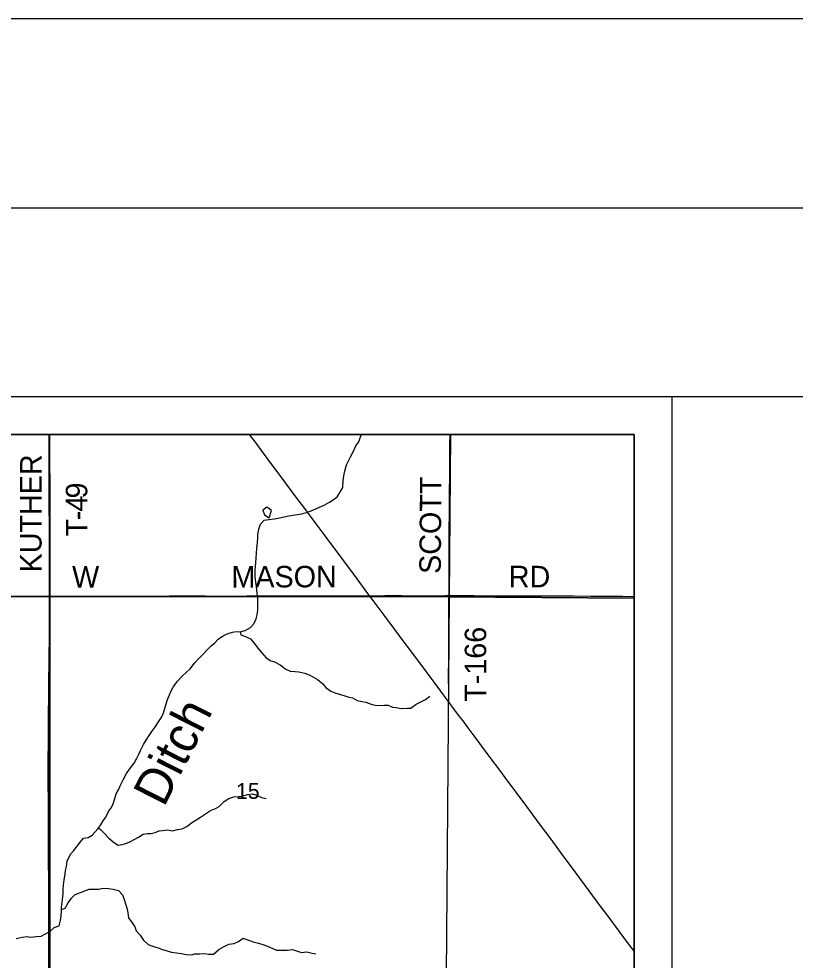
# Model space of a CAD drawing. Extents: x 0 to 1391, y -24 to 440.
# Drawn here: x 445.46 to 486.52, y 390.17 to 440 of the extents above; entities that cross this region are included whole.
import ezdxf

# ---------------------------------------------------------------- set-up
doc = ezdxf.new("R2010")
doc.units = 0
for name, color, linetype in [('Default', 7, 'Continuous'), ('GM_X_County_Road', 7, 'Continuous'), ('GM_X_County_Road_Text', 7, 'Continuous'), ('GM_X_Minor_Lake', 7, 'Continuous'), ('GM_X_Minor_River', 7, 'Continuous'), ('GM_X_Minor_River_Text', 7, 'Continuous'), ('GM_X_Section', 7, 'Continuous'), ('GM_X_Section_Text', 7, 'Continuous'), ('GM_X_State_Route', 7, 'Continuous'), ('GM_X_Township', 7, 'Continuous'), ('GM_X_Township_Road', 7, 'Continuous'), ('GM_X_Township_Road_Text', 7, 'Continuous'), ('SH_Border', 7, 'Continuous'), ('SH_Cut_Line', 7, 'Continuous'), ('SH_Data', 7, 'Continuous')]:
    doc.layers.add(name, color=color, linetype=linetype)

msp = doc.modelspace()

# ---------------------------------------------------------------- linework, layer by layer
at = {"layer": 'Default'}
msp.add_line((480, 420), (490, 420), dxfattribs=at)
at = {"layer": 'GM_X_County_Road'}
for points in [[(444.5, 409.44), (445.793, 409.438), (446.526, 409.432), (447.1, 409.437)], [(447.1, 409.437), (447.737, 409.441), (449.228, 409.441), (450.024, 409.439), (450.471, 409.445), (451.676, 409.442), (453.404, 409.448), (455.305, 409.45), (456.373, 409.446), (457.492, 409.453), (457.889, 409.452), (458.61, 409.453), (459.828, 409.457), (460.785, 409.457), (461.941, 409.458), (462.649, 409.459), (463.519, 409.456), (463.929, 409.458), (463.994, 409.459)], [(463.994, 409.459), (464.153, 409.461), (464.811, 409.468), (465.718, 409.467), (466.961, 409.464), (468.017, 409.467), (468.214, 409.466)], [(468.214, 409.466), (468.9, 409.465), (469.546, 409.465), (470.391, 409.462), (472.23, 409.462), (473.013, 409.458), (473.933, 409.457), (474.79, 409.452), (475.697, 409.444), (476.542, 409.439), (477.399, 409.433), (478, 409.426)]]:
    msp.add_lwpolyline(points, dxfattribs=at)
at = {"layer": 'GM_X_Minor_Lake'}
for points in [[(458.821, 413.968), (458.574, 414.149), (458.356, 413.993)], [(458.356, 413.993), (458.453, 413.735), (458.701, 413.586), (458.821, 413.968)]]:
    msp.add_lwpolyline(points, dxfattribs=at)
at = {"layer": 'GM_X_Minor_River'}
for points in [[(455.211, 406.369), (455.426, 406.594), (455.626, 406.812), (455.818, 406.969), (456.002, 407.164), (456.232, 407.328), (456.469, 407.446), (456.759, 407.534), (456.958, 407.562), (457.171, 407.559), (457.43, 407.617), (457.706, 407.773), (457.883, 407.976), (458.015, 408.247), (458.062, 408.451), (458.095, 408.693), (458.105, 409.027), (458.101, 409.36), (458.057, 409.588), (458.03, 409.952), (457.986, 410.173), (457.951, 410.484), (457.954, 410.832), (457.996, 411.211), (458.006, 411.476), (458.023, 411.711), (458.048, 411.968), (458.074, 412.286), (458.091, 412.513), (458.108, 412.71), (458.156, 412.983), (458.242, 413.247), (458.442, 413.457), (458.686, 413.499), (458.984, 413.534), (459.243, 413.584), (459.495, 413.642), (459.731, 413.692), (460.067, 413.741), (460.418, 413.805), (460.677, 413.871), (460.922, 413.959), (461.166, 414.07), (461.357, 414.158), (461.602, 414.254), (461.885, 414.41), (462.077, 414.544), (462.299, 414.693), (462.469, 414.972), (462.593, 415.19), (462.619, 415.569), (462.652, 415.803), (462.707, 416.053), (462.786, 416.385), (462.903, 416.611), (463.003, 416.815), (463.151, 417.109), (463.291, 417.395), (463.437, 417.613), (463.531, 417.87), (463.585, 418)], [(457.171, 407.559), (457.208, 407.391), (457.443, 407.312), (457.708, 407.171), (457.91, 406.955), (458.105, 406.679), (458.3, 406.449), (458.547, 406.18), (458.788, 406.009), (458.986, 405.96), (459.28, 405.804), (459.582, 405.572), (459.801, 405.47), (460.067, 405.443), (460.272, 405.439), (460.583, 405.366), (460.818, 405.271), (461.014, 405.17), (461.248, 405.022), (461.512, 404.813), (461.692, 404.606), (461.963, 404.412), (462.228, 404.309), (462.418, 404.253), (462.706, 404.165), (462.91, 404.086), (463.1, 404.06), (463.357, 403.919), (463.622, 403.87), (463.82, 403.821), (464.092, 403.726), (464.305, 403.677), (464.533, 403.651), (464.776, 403.677), (464.997, 403.673), (465.224, 403.556), (465.421, 403.538), (465.679, 403.496), (466.006, 403.513), (466.197, 403.518), (466.466, 403.726), (466.718, 403.836), (466.963, 403.976), (467.201, 404.146)], [(445.318, 391.311), (445.654, 391.391), (445.882, 391.418), (446.095, 391.386), (446.37, 391.42), (446.636, 391.44), (446.828, 391.544), (447.095, 391.693), (447.333, 391.895), (447.593, 391.983), (447.664, 392.27), (447.696, 392.52), (447.714, 392.785), (447.715, 392.982), (447.748, 393.248), (447.781, 393.52), (447.798, 393.717), (447.807, 393.93), (447.824, 394.142), (447.857, 394.414), (447.905, 394.717), (447.93, 394.914), (447.977, 395.133), (448.01, 395.414), (448.181, 395.776), (448.365, 395.978), (448.542, 396.196), (448.72, 396.429), (448.874, 396.625), (449.125, 396.66), (449.34, 396.794), (449.639, 397.116), (449.786, 397.334), (449.925, 397.538), (450.056, 397.741), (450.196, 398.042), (450.357, 398.245), (450.45, 398.441), (450.529, 398.721), (450.607, 398.97), (450.723, 399.189), (450.824, 399.4), (450.972, 399.709), (451.157, 400.056), (451.304, 400.282), (451.55, 400.59), (451.698, 400.868), (451.813, 401.072), (451.899, 401.268), (452.046, 401.585), (452.201, 401.81), (452.355, 402.066), (452.487, 402.277), (452.648, 402.487), (452.88, 402.841), (453.019, 403.059), (453.105, 403.271), (453.183, 403.497), (453.246, 403.731), (453.316, 403.966), (453.418, 404.222), (453.518, 404.426), (453.627, 404.629), (453.858, 404.945), (454.104, 405.207), (454.334, 405.409), (454.526, 405.589), (454.742, 405.89), (454.98, 406.137), (455.211, 406.369)], [(449.673, 397.167), (449.801, 397.07), (449.981, 396.87), (450.206, 396.654), (450.462, 396.415), (450.719, 396.251), (450.917, 396.294), (451.169, 396.365), (451.36, 396.446), (451.552, 396.564), (451.781, 396.674), (452.042, 396.837), (452.263, 396.871), (452.453, 396.868), (452.667, 396.933), (452.881, 397.013), (453.071, 397.04), (453.315, 397.074), (453.588, 397.017), (453.848, 397.088), (454.099, 397.13), (454.344, 397.247), (454.59, 397.433), (454.782, 397.559), (455.073, 397.743), (455.334, 397.914), (455.587, 398.084), (455.854, 398.201), (456.054, 398.312), (456.323, 398.573), (456.561, 398.721), (456.828, 398.815), (457.087, 398.826), (457.323, 398.875), (457.56, 398.947), (457.811, 398.966), (458.001, 398.917), (458.288, 398.784), (458.546, 398.734)], [(447.714, 392.848), (447.902, 392.929), (448.065, 393.2), (448.235, 393.447), (448.443, 393.641), (448.711, 393.743), (448.948, 393.838), (449.169, 393.933), (449.451, 393.928), (449.687, 393.932), (449.893, 393.982), (450.197, 393.962), (450.455, 393.927), (450.735, 393.862), (450.946, 393.623), (451.034, 393.379), (451.195, 392.861), (451.215, 392.671), (451.258, 392.405), (451.46, 392.151), (451.587, 391.937), (451.668, 391.723), (451.878, 391.5), (452.057, 391.224), (452.306, 391.007), (452.639, 390.873), (452.828, 390.825), (453.048, 390.73), (453.351, 390.642), (453.541, 390.601), (453.799, 390.566), (454.057, 390.524), (454.307, 390.467), (454.573, 390.448), (454.764, 390.505), (455.031, 390.509), (455.297, 390.519), (455.487, 390.486), (455.753, 390.482), (456.03, 390.728), (456.275, 390.883), (456.558, 391.015), (456.84, 391.056), (457.069, 391.151), (457.33, 391.337), (457.656, 391.217), (457.853, 391.146), (458.141, 391.073), (458.368, 390.994), (458.61, 390.906), (458.89, 390.781), (459.087, 390.702), (459.361, 390.697), (459.65, 390.7), (459.939, 390.726), (460.197, 390.638), (460.417, 390.567), (460.691, 390.608), (460.979, 390.535), (461.169, 390.501)]]:
    msp.add_lwpolyline(points, dxfattribs=at)
at = {"layer": 'GM_X_Section'}
for p, q in [((447.083, 418), (426.829, 418)), ((468.284, 418), (447.083, 418)), ((478, 389.026), (478, 409.34))]:
    msp.add_line(p, q, dxfattribs=at)
for points in [[(426.829, 418), (426.856, 409.369), (447.091, 409.422), (447.083, 418)], [(447.083, 418), (447.091, 409.422), (468.226, 409.405), (468.284, 418)], [(468.284, 418), (468.226, 409.405), (478, 409.34)], [(478, 409.34), (478, 418), (468.284, 418)], [(478, 409.34), (468.226, 409.405), (468.063, 389.349), (478, 389.026)]]:
    msp.add_lwpolyline(points, dxfattribs=at)
for points in [[(447.091, 409.422), (447.091, 389.196), (426.804, 389.204), (426.856, 409.369)], [(468.226, 409.405), (468.063, 389.349), (447.091, 389.196), (447.091, 409.422)]]:
    msp.add_lwpolyline(points, close=True, dxfattribs=at)
at = {"layer": 'GM_X_State_Route'}
msp.add_lwpolyline([(457.64, 418), (457.95, 417.584), (458.375, 417.002), (458.826, 416.408), (459.314, 415.749), (459.594, 415.369), (460.096, 414.705), (460.568, 414.079), (461.116, 413.341), (461.641, 412.632), (462.523, 411.445), (463.135, 410.615), (463.671, 409.898), (463.994, 409.459), (464.127, 409.277), (464.812, 408.362), (465.327, 407.676), (465.831, 406.998), (466.124, 406.612), (466.995, 405.432), (467.76, 404.406), (468.093, 403.956), (468.196, 403.817), (468.381, 403.567), (468.775, 403.054), (468.941, 402.837), (469.154, 402.546), (469.52, 402.044), (470.427, 400.829), (470.829, 400.292), (471.354, 399.583), (472.109, 398.564), (473.035, 397.317), (473.59, 396.568), (474.148, 395.821), (474.865, 394.853), (475.61, 393.843), (476.244, 392.983), (476.56, 392.567), (476.815, 392.23), (477.642, 391.111), (478, 390.634)], dxfattribs=at)
at = {"layer": 'GM_X_Township'}
for points in [[(447.02, 384.234), (447.036, 389.216), (447.076, 409.404), (447.056, 418), (367.289, 418), (367.16, 409.322), (367.112, 389.089), (367.052, 379.006), (366.961, 368.979), (366.895, 354.384)], [(447.056, 418), (447.076, 409.404), (447.036, 389.216), (451.2, 389.137), (459.724, 389.173), (463.069, 389.137), (465.594, 389.22), (467.732, 389.301), (470.436, 389.153), (473.97, 389.031), (478, 388.948)], [(478, 388.948), (478, 418), (447.056, 418)]]:
    msp.add_lwpolyline(points, dxfattribs=at)
at = {"layer": 'GM_X_Township_Road'}
for points in [[(447.1, 409.437), (447.101, 410.265), (447.103, 410.662), (447.11, 411.893), (447.113, 412.8), (447.111, 413.558), (447.113, 414.079), (447.108, 414.564), (447.107, 415.67), (447.103, 416.204), (447.094, 416.875), (447.09, 417.559), (447.087, 418)], [(468.214, 409.466), (468.217, 410.587), (468.22, 411.034), (468.221, 411.593), (468.227, 412.911), (468.232, 413.843), (468.239, 414.563), (468.25, 416.166), (468.261, 417.446), (468.267, 418)], [(447.063, 389.854), (447.065, 390.314), (447.062, 391.022), (447.058, 391.308), (447.057, 391.569), (447.056, 391.979), (447.056, 392.476), (447.056, 393.222), (447.044, 394.005), (447.038, 394.539), (447.028, 395.31), (447.026, 396.043), (447.022, 396.714), (447.019, 397.112), (447.019, 397.622), (447.018, 398.678), (447.014, 399.486), (447.013, 400.741), (447.019, 401.736), (447.026, 402.395), (447.031, 403.19), (447.04, 404.085), (447.04, 404.408), (447.042, 404.656), (447.05, 405.079), (447.061, 405.812), (447.068, 406.483), (447.078, 407.005), (447.085, 407.95), (447.089, 408.77), (447.092, 409.18), (447.1, 409.437)], [(468.196, 403.817), (468.196, 404.075), (468.195, 404.348), (468.191, 405.218), (468.197, 406.088), (468.201, 406.909), (468.206, 408.164), (468.204, 408.723), (468.21, 409.257), (468.214, 409.466)]]:
    msp.add_lwpolyline(points, dxfattribs=at)
at = {"layer": 'SH_Border'}
msp.add_lwpolyline([(30, 430), (670, 430), (670, 10), (30, 10)], close=True, dxfattribs=at)
at = {"layer": 'SH_Cut_Line'}
msp.add_lwpolyline([(0, 0), (680, 0), (680, 440), (0, 440)], close=True, dxfattribs=at)
at = {"layer": 'SH_Data'}
for p, q in [((340, 420), (480, 420)), ((480, 420), (480, 280)), ((342, 418), (478, 418)), ((478, 418), (478, 282))]:
    msp.add_line(p, q, dxfattribs=at)

# ---------------------------------------------------------------- texts
at = {"layer": 'GM_X_County_Road_Text'}
for s, height, rotation, p in [('W', 1.136, 0, (448.274, 409.893)), ('MASON', 1.1364, 0.1896, (456.704, 409.893)), ('RD', 1.1364, 0, (471.374, 409.909))]:
    msp.add_text(s, height=height, rotation=rotation, dxfattribs=at).set_placement(p)
at = {"layer": 'GM_X_Minor_River_Text'}
msp.add_text('Ditch', height=1.8944, rotation=63.0608, dxfattribs=at).set_placement((453.128, 398.221))
at = {"layer": 'GM_X_Section_Text'}
msp.add_text('15', height=0.8371, rotation=0, dxfattribs=at).set_placement((456.949, 398.707))
at = {"layer": 'GM_X_Township_Road_Text'}
for s, height, rotation, p in [('KUTHER', 1.1364, 90, (446.66, 410.696)), ('SCOTT', 1.1364, 89.5644, (467.776, 410.613)), ('9', 1.136, 90.1384, (449.079, 414.61)), ('4', 1.136, 90.1203, (449.08, 413.915)), ('-', 1.136, 90.0954, (449.081, 413.452)), ('T', 1.136, 90.0354, (449.081, 412.602)), ('T-166', 1.1364, 90, (470.179, 403.846))]:
    msp.add_text(s, height=height, rotation=rotation, dxfattribs=at).set_placement(p)

doc.saveas('drawing.dxf')
